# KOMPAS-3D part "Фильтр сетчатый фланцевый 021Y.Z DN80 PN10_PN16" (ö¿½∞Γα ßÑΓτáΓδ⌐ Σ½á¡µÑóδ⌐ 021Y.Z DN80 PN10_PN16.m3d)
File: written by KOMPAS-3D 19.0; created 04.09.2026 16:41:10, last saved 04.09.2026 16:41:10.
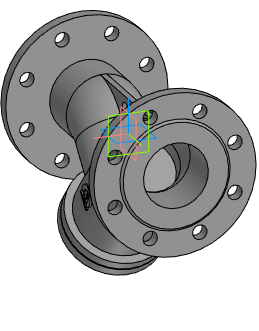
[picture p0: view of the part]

Document properties: Автор: Энергия; Полное имя файла: Z:\3.Личные\sachek\Dendor\_3D для проектировщиков\8.1 Фильтр сетчатый 021Y.Z\021Y.Z_STP\Фильтр сетчатый фланцевый 021Y.Z DN80 PN10_PN16.m3d

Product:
- Part/product: Фильтр сетчатый фланцевый 021Y.Z DN80 PN10_PN16

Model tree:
1. Операция без истории:1  (labels: Фильтр сетчатый фланцевый 021Y.Z DN80 PN10_PN16)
